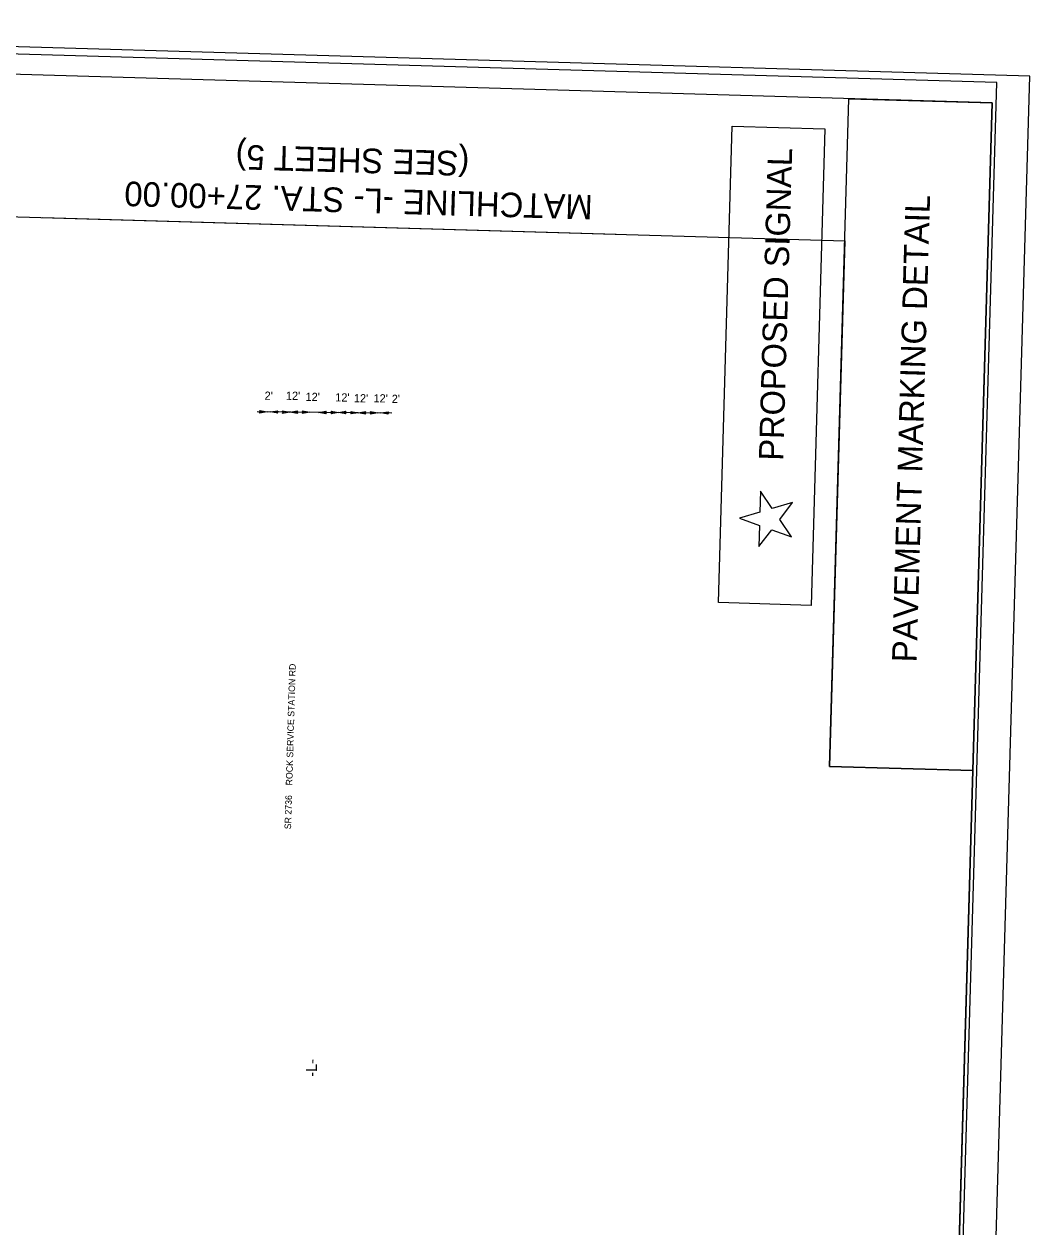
# Model space of a CAD drawing. Extents: x 2097002 to 2098146, y 685127 to 687089.
# Drawn here: x 2097532 to 2098146, y 686108 to 686842 of the extents above; entities that cross this region are included whole.
import ezdxf

# ---------------------------------------------------------------- set-up
doc = ezdxf.new("R2010")
doc.units = 0
for name, color, linetype in [('Default', 7, 'Continuous'), ('Matchline', 7, 'Continuous'), ('Matchline Text', 7, 'Continuous'), ('Prop Horizontal Alignment Station Label', 7, 'Continuous'), ('Sheet Layout Plan Border', 7, 'Continuous'), ('Sheet Plan CELL', 7, 'Continuous'), ('Sheet Plot Border Inside CELL', 7, 'Continuous'), ('Sheet Plot Border Outside CELL', 7, 'Continuous'), ('Text', 7, 'Continuous')]:
    doc.layers.add(name, color=color, linetype=linetype)

msp = doc.modelspace()

# ---------------------------------------------------------------- linework, layer by layer
at = {"layer": 'Default'}
msp.add_line((2097756.01, 686604.64), (2097673.79, 686605.38), dxfattribs=at)
for points in [[(2097955.43, 686488.97), (2097963.88, 686779.73), (2098020.4, 686778.09), (2098011.94, 686487.32)], [(2097675.42, 686606.14), (2097679.91, 686605.33), (2097675.38, 686604.57), (2097675.96, 686605.36)], [(2097686.48, 686604.49), (2097681.99, 686605.31), (2097686.52, 686606.07), (2097685.94, 686605.27)], [(2097689.42, 686606.02), (2097693.91, 686605.2), (2097689.38, 686604.44), (2097689.96, 686605.24)], [(2097698.41, 686604.38), (2097693.92, 686605.2), (2097698.45, 686605.96), (2097697.87, 686605.16)], [(2097701.56, 686605.9), (2097706.05, 686605.09), (2097701.52, 686604.33), (2097702.1, 686605.12)], [(2097715.92, 686604.22), (2097711.42, 686605.04), (2097715.96, 686605.8), (2097715.37, 686605)], [(2097719.07, 686605.77), (2097723.56, 686604.95), (2097719.03, 686604.19), (2097719.61, 686604.99)], [(2097727.92, 686604.11), (2097723.43, 686604.93), (2097727.96, 686605.69), (2097727.38, 686604.89)], [(2097731.07, 686605.66), (2097735.56, 686604.84), (2097731.03, 686604.08), (2097731.61, 686604.88)], [(2097739.92, 686604.01), (2097735.43, 686604.82), (2097739.96, 686605.58), (2097739.38, 686604.79)], [(2097743.07, 686605.55), (2097747.56, 686604.74), (2097743.03, 686603.98), (2097743.61, 686604.77)], [(2097753.92, 686603.88), (2097749.43, 686604.69), (2097753.96, 686605.45), (2097753.38, 686604.66)]]:
    msp.add_lwpolyline(points, close=True, dxfattribs=at)
msp.add_lwpolyline([(2097980.38, 686536.08), (2097980.01, 686523.17), (2097987.9, 686533.4), (2098000.09, 686529.04), (2097992.79, 686539.74), (2098000.69, 686549.98), (2097988.28, 686546.34), (2097980.98, 686557.01), (2097980.61, 686544.09), (2097968.19, 686540.44), (2097980.38, 686536.08)], dxfattribs=at)
at = {"layer": 'Matchline'}
msp.add_line((2097543.06, 686723.93), (2097892.91, 686713.76), dxfattribs=at)
at = {"layer": 'Sheet Layout Plan Border'}
msp.add_lwpolyline([(2098110.68, 686386.52), (2098090.85, 685704.42), (2097236.93, 685318.96), (2097029.37, 685324.99), (2097061.33, 686424.42), (2097062.77, 686473.85), (2097066.87, 686614.87), (2097306.86, 686607.89), (2097310.43, 686730.69), (2098032.53, 686709.7), (2098023.21, 686389.06)], close=True, dxfattribs=at)
at = {"layer": 'Sheet Plan CELL'}
for p, q in [((2098122.52, 686793.84), (2097072.96, 686824.36)), ((2098078.93, 685294.46), (2098122.52, 686793.84))]:
    msp.add_line(p, q, dxfattribs=at)
msp.add_lwpolyline([(2098122.52, 686793.84), (2098110.68, 686386.52), (2098023.21, 686389.06), (2098035.05, 686796.39)], close=True, dxfattribs=at)
at = {"layer": 'Sheet Plot Border Inside CELL'}
msp.add_lwpolyline([(2098076.98, 685140.97), (2098125.38, 686806.22), (2097070.84, 686836.88), (2097022.43, 685171.63)], close=True, dxfattribs=at)
at = {"layer": 'Sheet Plot Border Outside CELL'}
msp.add_lwpolyline([(2098096.59, 685127.4), (2098145.51, 686810.14), (2097050.98, 686841.96), (2097002.06, 685159.22)], close=True, dxfattribs=at)

# ---------------------------------------------------------------- texts
at = {"layer": 'Default'}
msp.add_text('PROPOSED SIGNAL', height=14.8414, rotation=88.33483, dxfattribs=at).set_placement((2097994.9, 686575.42))
at = {"layer": 'Matchline Text'}
for s, p in [('(SEE SHEET 5)', (2097803.54, 686764.25)), ('MATCHLINE -L- STA. 27+00.00', (2097878.9, 686737.67))]:
    msp.add_text(s, height=15, rotation=178.33483, dxfattribs=at).set_placement(p)
at = {"layer": 'Prop Horizontal Alignment Station Label'}
msp.add_text('-L-', height=6.641, rotation=88.86596, dxfattribs=at).set_placement((2097710.26, 686199.63))
at = {"layer": 'Text'}
for s, height, rotation, p in [('PAVEMENT MARKING DETAIL', 15, 88.33483, (2098076.32, 686452.37)), ("2'", 5, 359.48075, (2097678.43, 686612.76)), ("12'", 5, 359.48075, (2097691.41, 686612.72)), ("12'", 5, 359.48075, (2097703.4, 686612.05)), ("12'", 5, 359.48075, (2097721.53, 686611.72)), ("12'", 5, 359.48075, (2097732.89, 686611.19)), ("12'", 5, 359.48075, (2097744.89, 686611.17)), ("2'", 5, 359.48075, (2097756.01, 686610.82)), ('SR 2736    ROCK SERVICE STATION RD   ', 4, 88.33483, (2097694.55, 686350.66))]:
    msp.add_text(s, height=height, rotation=rotation, dxfattribs=at).set_placement(p)

doc.saveas('drawing.dxf')
